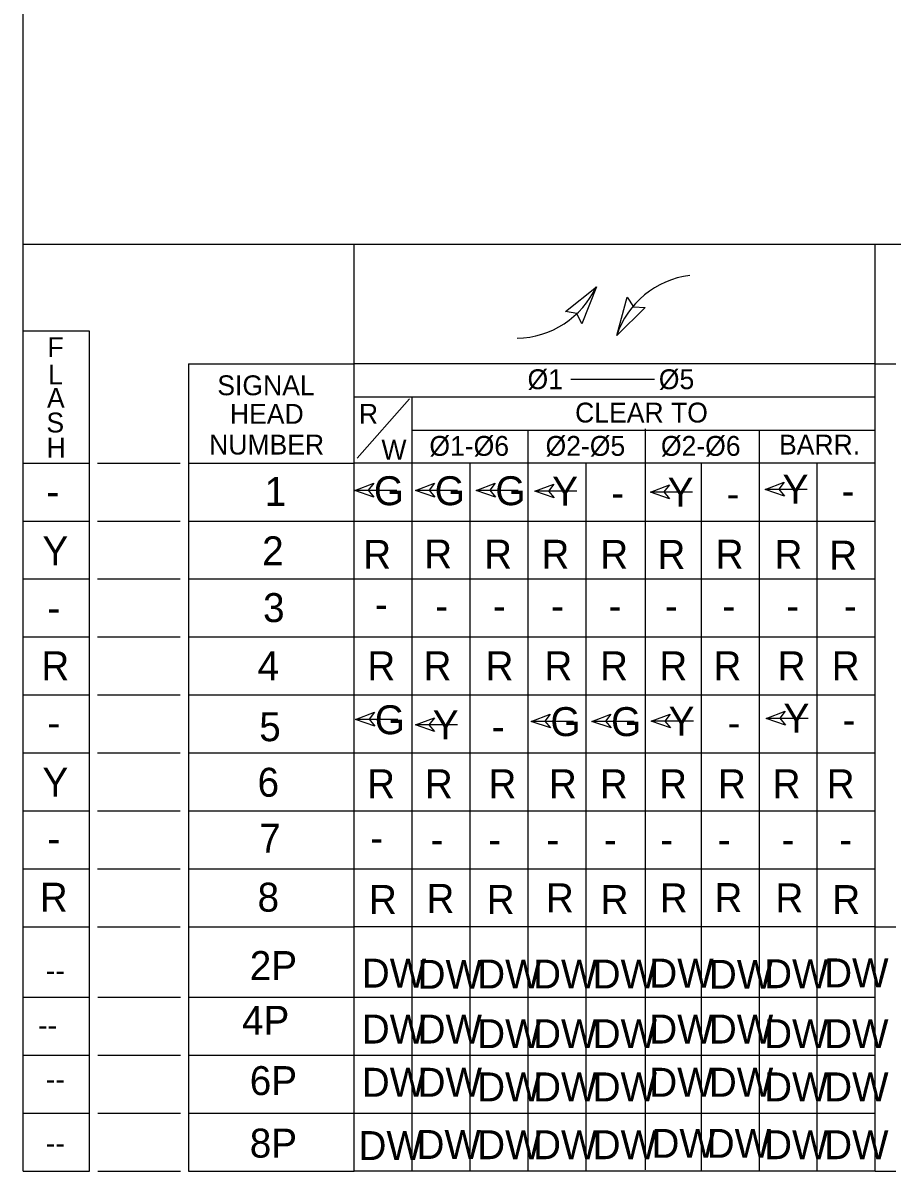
# Model space of a CAD drawing. Extents: x 0 to 3.01, y -0.05 to 1.83.
# Drawn here: x 2.2984 to 2.5103, y 1.2634 to 1.5432 of the extents above; entities that cross this region are included whole.
import ezdxf

# ---------------------------------------------------------------- set-up
doc = ezdxf.new("R2010")
doc.units = 0
for name, color, linetype in [('TR_TS_Border', 7, 'Continuous'), ('TR_TS_Phase1', 7, 'Continuous'), ('TR_TS_Phase2', 7, 'Continuous'), ('TR_TS_Phase3', 7, 'Continuous'), ('TR_TS_Phase4', 7, 'Continuous'), ('TR_TS_Phase5', 7, 'Continuous'), ('TR_TS_Phase6', 7, 'Continuous'), ('TR_TS_Phase7', 7, 'Continuous'), ('TR_TS_Phase8', 7, 'Continuous')]:
    doc.layers.add(name, color=color, linetype=linetype)

msp = doc.modelspace()

# ---------------------------------------------------------------- linework, layer by layer
at = {"layer": 'TR_TS_Border'}
for p, q in [((2.2983729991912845, 1.6927997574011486), (2.2983729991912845, 1.2634424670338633)), ((2.9074756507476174, 1.4891940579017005), (2.2983729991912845, 1.4891940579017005)), ((2.3790452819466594, 1.489194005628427), (2.3790452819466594, 1.2634422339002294)), ((2.506117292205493, 1.4891941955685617), (2.506117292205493, 1.2634424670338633)), ((2.2983729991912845, 1.4681904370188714), (2.31450758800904, 1.4681904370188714)), ((2.31450758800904, 1.4681904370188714), (2.31450758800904, 1.2634424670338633)), ((2.3387092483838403, 1.4601230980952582), (2.3790452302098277, 1.4601230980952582)), ((2.3387092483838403, 1.4601230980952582), (2.3387092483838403, 1.2634424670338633)), ((2.506117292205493, 1.4601230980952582), (2.3790452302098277, 1.4601230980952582)), ((2.506117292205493, 1.4601230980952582), (2.511179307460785, 1.4601230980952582)), ((2.431951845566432, 1.4563796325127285), (2.4523735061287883, 1.4563796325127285)), ((2.3790452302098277, 1.4520558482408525), (2.506117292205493, 1.4520558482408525)), ((2.3931761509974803, 1.4520558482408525), (2.3931761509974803, 1.2634424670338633)), ((2.379888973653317, 1.4371341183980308), (2.3925961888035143, 1.4515814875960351)), ((2.3931761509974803, 1.4439888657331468), (2.506117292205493, 1.4439888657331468)), ((2.421463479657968, 1.4439888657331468), (2.421463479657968, 1.2634424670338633)), ((2.450122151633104, 1.444253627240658), (2.450122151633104, 1.2637072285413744)), ((2.477908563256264, 1.4439888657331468), (2.477908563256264, 1.2634424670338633)), ((2.2983729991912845, 1.4359214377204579), (2.31450758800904, 1.4359214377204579)), ((2.316563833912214, 1.4359214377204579), (2.3367054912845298, 1.4359214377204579)), ((2.3387092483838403, 1.4359214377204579), (2.3790452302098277, 1.4359214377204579)), ((2.506117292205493, 1.4359214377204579), (2.3790452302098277, 1.4359214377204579)), ((2.4073326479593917, 1.4359214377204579), (2.4073326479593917, 1.2634424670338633)), ((2.435594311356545, 1.4359214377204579), (2.435594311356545, 1.2634424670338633)), ((2.463777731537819, 1.4359214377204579), (2.463777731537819, 1.2634424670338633)), ((2.4919864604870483, 1.4359214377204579), (2.4919864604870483, 1.2634424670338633)), ((2.2983729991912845, 1.4217904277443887), (2.31450758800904, 1.4217904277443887)), ((2.316563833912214, 1.4217904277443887), (2.3367054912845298, 1.4217904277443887)), ((2.3387092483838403, 1.4217904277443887), (2.506117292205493, 1.4217904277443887)), ((2.2983729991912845, 1.4077126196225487), (2.31450758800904, 1.4077126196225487)), ((2.316563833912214, 1.4077126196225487), (2.3367054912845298, 1.4077126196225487)), ((2.3387092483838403, 1.4077126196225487), (2.506117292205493, 1.4077126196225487)), ((2.2983729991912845, 1.39358169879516), (2.31450758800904, 1.39358169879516)), ((2.316563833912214, 1.39358169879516), (2.3367054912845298, 1.39358169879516)), ((2.3387092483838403, 1.39358169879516), (2.506117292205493, 1.39358169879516)), ((2.2983729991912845, 1.3794506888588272), (2.31450758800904, 1.3794506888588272)), ((2.316563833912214, 1.3794506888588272), (2.3367054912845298, 1.3794506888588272)), ((2.3387092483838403, 1.3794506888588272), (2.506117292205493, 1.3794506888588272)), ((2.2983729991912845, 1.365372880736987), (2.31450758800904, 1.365372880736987)), ((2.316563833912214, 1.365372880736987), (2.3367054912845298, 1.365372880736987)), ((2.3387092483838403, 1.365372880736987), (2.506117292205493, 1.365372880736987)), ((2.2983729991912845, 1.3512419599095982), (2.31450758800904, 1.3512419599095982)), ((2.316563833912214, 1.3512419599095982), (2.3367054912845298, 1.3512419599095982)), ((2.3387092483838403, 1.3512419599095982), (2.506117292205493, 1.3512419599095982)), ((2.2983729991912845, 1.3371109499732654), (2.31450758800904, 1.3371109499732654)), ((2.316563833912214, 1.3371109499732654), (2.3367054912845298, 1.3371109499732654)), ((2.3387092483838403, 1.3371109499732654), (2.506117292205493, 1.3371109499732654)), ((2.2983729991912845, 1.3229801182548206), (2.31450758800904, 1.3229801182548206)), ((2.316563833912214, 1.3229801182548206), (2.3367054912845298, 1.3229801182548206)), ((2.3387092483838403, 1.3229801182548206), (2.3790452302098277, 1.3229801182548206)), ((2.506117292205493, 1.3229801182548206), (2.3790452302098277, 1.3229801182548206)), ((2.506117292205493, 1.3229801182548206), (2.511179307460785, 1.3229801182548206)), ((2.298446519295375, 1.3058350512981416), (2.3145809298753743, 1.3058350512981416)), ((2.3166371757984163, 1.3058350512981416), (2.3367790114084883, 1.3058350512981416)), ((2.3387825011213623, 1.3058350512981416), (2.5061908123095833, 1.3058350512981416)), ((2.298446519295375, 1.2917041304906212), (2.3145809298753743, 1.2917041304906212)), ((2.3166371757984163, 1.2917041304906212), (2.3367790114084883, 1.2917041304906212)), ((2.3387825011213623, 1.2917041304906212), (2.5061908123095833, 1.2917041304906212)), ((2.298446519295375, 1.2775732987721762), (2.3145809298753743, 1.2775732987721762)), ((2.3166371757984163, 1.2775732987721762), (2.3367790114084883, 1.2775732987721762)), ((2.3387825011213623, 1.2775732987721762), (2.5061908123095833, 1.2775732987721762)), ((2.298446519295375, 1.2634424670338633), (2.3145809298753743, 1.2634424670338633)), ((2.3166371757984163, 1.2634424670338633), (2.3367790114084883, 1.2634424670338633)), ((2.3387825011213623, 1.2634424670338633), (2.379118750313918, 1.2634424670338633)), ((2.5061908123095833, 1.2634424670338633), (2.379118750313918, 1.2634424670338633)), ((2.5061908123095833, 1.2634424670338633), (2.5112527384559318, 1.2634424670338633))]:
    msp.add_line(p, q, dxfattribs=at)
at = {"layer": 'TR_TS_Phase1'}
for p, q in [((2.443227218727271, 1.4670472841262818), (2.4457458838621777, 1.4764021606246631)), ((2.4457458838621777, 1.4764021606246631), (2.4472570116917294, 1.474027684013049)), ((2.4500635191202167, 1.4738835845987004), (2.443227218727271, 1.4670472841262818)), ((2.4472570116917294, 1.474027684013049), (2.4500635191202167, 1.4738835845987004)), ((2.3792730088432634, 1.429266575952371), (2.3839074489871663, 1.4310291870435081)), ((2.3839074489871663, 1.4310291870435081), (2.382578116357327, 1.429325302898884)), ((2.394104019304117, 1.429266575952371), (2.398738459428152, 1.4310291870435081)), ((2.398738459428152, 1.4310291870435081), (2.3974091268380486, 1.429325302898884)), ((2.4088973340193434, 1.429266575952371), (2.4135318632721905, 1.4310291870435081)), ((2.4135318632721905, 1.4310291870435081), (2.4122024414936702, 1.429325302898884)), ((2.4232014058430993, 1.429071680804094), (2.4278357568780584, 1.4308344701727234)), ((2.4278357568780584, 1.4308344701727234), (2.4265065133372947, 1.4291304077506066)), ((2.451357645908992, 1.4288440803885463), (2.4559920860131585, 1.4306066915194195)), ((2.4559920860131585, 1.4306066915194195), (2.4546627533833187, 1.4289028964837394)), ((2.479378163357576, 1.4295275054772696), (2.484012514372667, 1.4312901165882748)), ((2.489639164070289, 1.4295275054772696), (2.479378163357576, 1.4295275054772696)), ((2.4840565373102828, 1.4279189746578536), (2.479378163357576, 1.4295275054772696)), ((2.484012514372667, 1.4312901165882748), (2.4826832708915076, 1.4295862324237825)), ((2.4826832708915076, 1.4295862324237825), (2.4840565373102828, 1.4279189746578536)), ((2.389534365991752, 1.429266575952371), (2.3792730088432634, 1.429266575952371)), ((2.383951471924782, 1.4276580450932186), (2.3792730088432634, 1.429266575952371)), ((2.382578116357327, 1.429325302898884), (2.383951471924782, 1.4276580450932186)), ((2.404365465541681, 1.429266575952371), (2.394104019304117, 1.429266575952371)), ((2.3987824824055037, 1.4276580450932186), (2.394104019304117, 1.429266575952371)), ((2.3974091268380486, 1.429325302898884), (2.3987824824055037, 1.4276580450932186)), ((2.4191586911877, 1.429266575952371), (2.4088973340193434, 1.429266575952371)), ((2.4135758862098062, 1.4276580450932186), (2.4088973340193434, 1.429266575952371)), ((2.4122024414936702, 1.429325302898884), (2.4135758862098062, 1.4276580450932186)), ((2.4334624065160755, 1.429071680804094), (2.4232014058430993, 1.429071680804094)), ((2.427879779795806, 1.4274633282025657), (2.4232014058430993, 1.429071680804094)), ((2.4265065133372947, 1.4291304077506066), (2.427879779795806, 1.4274633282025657)), ((2.46161873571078, 1.4288440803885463), (2.451357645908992, 1.4288440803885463)), ((2.456036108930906, 1.4272355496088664), (2.451357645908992, 1.4288440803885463)), ((2.4546627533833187, 1.4289028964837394), (2.456036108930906, 1.4272355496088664))]:
    msp.add_line(p, q, dxfattribs=at)
msp.add_arc((2.4636753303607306, 1.4602126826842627), 0.021617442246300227, 97.19140000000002, 161.63656666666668, dxfattribs=at)
at = {"layer": 'TR_TS_Phase5'}
for p, q in [((2.430661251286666, 1.4728688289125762), (2.4382011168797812, 1.4789204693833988)), ((2.4382011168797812, 1.4789204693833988), (2.434679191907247, 1.4698954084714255)), ((2.4334351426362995, 1.4724204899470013), (2.430661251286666, 1.4728688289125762)), ((2.434679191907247, 1.4698954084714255), (2.4334351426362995, 1.4724204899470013)), ((2.379500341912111, 1.3734607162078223), (2.3841347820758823, 1.3752235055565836)), ((2.3841347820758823, 1.3752235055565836), (2.382805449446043, 1.3735194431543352)), ((2.3940697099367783, 1.37212728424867), (2.398704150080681, 1.3738898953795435)), ((2.398704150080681, 1.3738898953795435), (2.397374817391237, 1.3721861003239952)), ((2.422325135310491, 1.3730050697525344), (2.426959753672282, 1.3747678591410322)), ((2.426959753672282, 1.3747678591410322), (2.4256302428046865, 1.3730637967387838)), ((2.4371185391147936, 1.3730050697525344), (2.4417531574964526, 1.3747678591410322)), ((2.4417531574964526, 1.3747678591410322), (2.4404236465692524, 1.3730637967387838)), ((2.4515850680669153, 1.3730382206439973), (2.456219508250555, 1.3748010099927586)), ((2.456219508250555, 1.3748010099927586), (2.454890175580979, 1.3730970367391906)), ((2.479605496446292, 1.3737216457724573), (2.4842399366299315, 1.375484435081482)), ((2.4898665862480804, 1.3737216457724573), (2.479605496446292, 1.3737216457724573)), ((2.4842839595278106, 1.3721131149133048), (2.479605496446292, 1.3737216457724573)), ((2.4842399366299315, 1.375484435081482), (2.4829106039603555, 1.3737803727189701)), ((2.4829106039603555, 1.3737803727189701), (2.4842839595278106, 1.3721131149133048)), ((2.3897617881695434, 1.3734607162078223), (2.379500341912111, 1.3734607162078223)), ((2.384178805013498, 1.3718523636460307), (2.379500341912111, 1.3734607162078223)), ((2.382805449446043, 1.3735194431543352), (2.384178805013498, 1.3718523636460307)), ((2.4043307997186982, 1.37212728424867), (2.3940697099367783, 1.37212728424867)), ((2.398748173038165, 1.3705187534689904), (2.3940697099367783, 1.37212728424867)), ((2.397374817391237, 1.3721861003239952), (2.398748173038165, 1.3705187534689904)), ((2.4325865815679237, 1.3730050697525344), (2.422325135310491, 1.3730050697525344)), ((2.4270037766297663, 1.3713965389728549), (2.422325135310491, 1.3730050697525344)), ((2.4256302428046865, 1.3730637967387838), (2.4270037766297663, 1.3713965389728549)), ((2.4473799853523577, 1.3730050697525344), (2.4371185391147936, 1.3730050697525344)), ((2.4417971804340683, 1.3713965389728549), (2.4371185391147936, 1.3730050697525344)), ((2.4404236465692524, 1.3730637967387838), (2.4417971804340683, 1.3713965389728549)), ((2.4618461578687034, 1.3730382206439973), (2.4515850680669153, 1.3730382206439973)), ((2.456263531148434, 1.3714296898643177), (2.4515850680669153, 1.3730382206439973)), ((2.454890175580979, 1.3730970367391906), (2.456263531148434, 1.3714296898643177))]:
    msp.add_line(p, q, dxfattribs=at)
msp.add_arc((2.4185162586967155, 1.4879885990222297), 0.021617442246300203, 270.9422666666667, 335.3874333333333, dxfattribs=at)

# ---------------------------------------------------------------- texts
at = {"layer": 'TR_TS_Border'}
for s, height, p in [('F', 0.004840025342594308, (2.304358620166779, 1.461756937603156)), ('L', 0.004840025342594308, (2.304483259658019, 1.4551132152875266)), ('Ø1             Ø5', 0.0048400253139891, (2.4214199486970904, 1.4539533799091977)), ('SIGNAL', 0.004840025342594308, (2.3457735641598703, 1.4524770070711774)), ('A', 0.004840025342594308, (2.304238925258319, 1.4494186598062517)), ('HEAD', 0.004840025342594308, (2.3488477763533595, 1.445516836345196)), ('R', 0.004840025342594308, (2.3802960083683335, 1.445516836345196)), ('CLEAR TO', 0.004840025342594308, (2.4330137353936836, 1.445833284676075)), ('S', 0.004840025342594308, (2.3040980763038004, 1.4434078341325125)), ('H', 0.004840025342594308, (2.3041231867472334, 1.437291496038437)), ('NUMBER', 0.004840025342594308, (2.3437709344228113, 1.438029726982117)), ('W', 0.004840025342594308, (2.385790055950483, 1.4368168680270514)), ('Ø1-Ø6', 0.004840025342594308, (2.39748467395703, 1.4377132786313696)), ('Ø2-Ø5', 0.004840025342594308, (2.4258099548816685, 1.4377132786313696)), ('Ø2-Ø6', 0.004840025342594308, (2.4539404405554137, 1.4377132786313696)), ('BARR.', 0.004840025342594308, (2.4827314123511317, 1.438029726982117))]:
    msp.add_text(s, height=height, rotation=360, dxfattribs=at).set_placement(p)
at = {"layer": 'TR_TS_Phase1'}
for s, p in [('1', (2.3573268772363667, 1.4255008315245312)), ('G', (2.3839499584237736, 1.4256844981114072)), ('G', (2.3987814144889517, 1.4256844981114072)), ('G', (2.4135748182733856, 1.4256844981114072)), ('Y', (2.4274309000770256, 1.4255827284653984)), ('Y', (2.4555873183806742, 1.4253552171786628)), ('Y', (2.4836076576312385, 1.426038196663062)), ('-', (2.3040972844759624, 1.4255008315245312)), ('-', (2.4418011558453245, 1.4252290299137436)), ('-', (2.4699575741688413, 1.4250015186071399)), ('-', (2.497977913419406, 1.4256844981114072))]:
    msp.add_text(s, height=0.007050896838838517, dxfattribs=at).set_placement(p)
at = {"layer": 'TR_TS_Phase2'}
for s, p in [('Y', (2.303127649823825, 1.4110400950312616)), ('2', (2.356703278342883, 1.4110400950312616))]:
    msp.add_text(s, height=0.007050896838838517, rotation=360, dxfattribs=at).set_placement(p)
for s, height, p in [('R', 0.007050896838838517, (2.381338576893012, 1.410179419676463)), ('R', 0.007050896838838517, (2.396208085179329, 1.4102638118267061)), ('R', 0.007050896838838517, (2.410811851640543, 1.4102436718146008)), ('R', 0.007050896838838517, (2.4248000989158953, 1.410204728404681)), ('R', 0.007050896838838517, (2.4391508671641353, 1.4101844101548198)), ('R', 0.007050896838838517, (2.453096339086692, 1.4101705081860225)), ('R', 0.007050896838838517, (2.467278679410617, 1.4102344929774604)), ('R', 0.007050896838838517, (2.4816307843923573, 1.410179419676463)), ('R', 0.007050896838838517, (2.494970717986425, 1.4099906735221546)), ('2P', 0.007050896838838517, (2.3536801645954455, 1.3099869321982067)), ('DW', 0.007050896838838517, (2.38099742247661, 1.3081454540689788)), ('DW', 0.007050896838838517, (2.3946009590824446, 1.3078440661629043)), ('DW', 0.007050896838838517, (2.40912897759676, 1.3079223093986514)), ('DW', 0.007050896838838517, (2.4227583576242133, 1.3079223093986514)), ('DW', 0.007050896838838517, (2.4372864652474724, 1.3079223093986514)), ('DW', 0.007050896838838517, (2.4510975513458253, 1.3081454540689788)), ('DW', 0.007050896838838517, (2.465625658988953, 1.3078440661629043)), ('DW', 0.007050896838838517, (2.4790991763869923, 1.3079986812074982)), ('DW', 0.007050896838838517, (2.493740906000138, 1.3081925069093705)), ('--', 0.005251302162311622, (2.30391307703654, 1.3097177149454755))]:
    msp.add_text(s, height=height, dxfattribs=at).set_placement(p)
at = {"layer": 'TR_TS_Phase3'}
for s, p in [('3', (2.3569246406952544, 1.3972038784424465)), ('-', (2.304338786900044, 1.3972038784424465)), ('-', (2.38420202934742, 1.3980887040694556)), ('-', (2.3989235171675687, 1.3976877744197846)), ('-', (2.412957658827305, 1.3976877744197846)), ('-', (2.427144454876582, 1.3976877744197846)), ('-', (2.441178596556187, 1.3976877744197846)), ('-', (2.454901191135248, 1.3976877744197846)), ('-', (2.468935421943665, 1.3976877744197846)), ('-', (2.484514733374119, 1.3976877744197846)), ('-', (2.4985490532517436, 1.3976877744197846))]:
    msp.add_text(s, height=0.007050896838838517, dxfattribs=at).set_placement(p)
at = {"layer": 'TR_TS_Phase4'}
for s, p in [('R', (2.3028560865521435, 1.3830324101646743)), ('4', (2.355583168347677, 1.3830324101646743)), ('R', (2.382351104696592, 1.3830324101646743)), ('R', (2.3960480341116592, 1.3830324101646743)), ('R', (2.4111716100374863, 1.3830324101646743)), ('R', (2.425519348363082, 1.3830324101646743)), ('R', (2.439091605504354, 1.3830324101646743)), ('R', (2.453557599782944, 1.3830324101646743)), ('R', (2.4667421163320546, 1.3830324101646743)), ('R', (2.482398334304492, 1.3830324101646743)), ('R', (2.4955828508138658, 1.3830324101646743))]:
    msp.add_text(s, height=0.007050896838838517, rotation=360, dxfattribs=at).set_placement(p)
for s, height, p in [('4P', 0.007050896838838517, (2.351795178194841, 1.2966357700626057)), ('DW', 0.007050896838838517, (2.38099742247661, 1.2945137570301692)), ('DW', 0.007050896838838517, (2.3946009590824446, 1.2945137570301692)), ('DW', 0.007050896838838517, (2.4510975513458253, 1.2945137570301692)), ('DW', 0.007050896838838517, (2.465625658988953, 1.2945137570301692)), ('--', 0.005251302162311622, (2.302028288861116, 1.296366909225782)), ('DW', 0.007050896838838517, (2.40912897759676, 1.2933867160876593)), ('DW', 0.007050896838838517, (2.4227583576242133, 1.2933867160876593)), ('DW', 0.007050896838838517, (2.4372864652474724, 1.2933867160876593)), ('DW', 0.007050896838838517, (2.4790991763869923, 1.2933867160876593)), ('DW', 0.007050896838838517, (2.493740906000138, 1.2933867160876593))]:
    msp.add_text(s, height=height, dxfattribs=at).set_placement(p)
at = {"layer": 'TR_TS_Phase5'}
for s, p in [('G', (2.384177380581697, 1.3698789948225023)), ('G', (2.4270023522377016, 1.369423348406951)), ('G', (2.4417957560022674, 1.369423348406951)), ('Y', (2.4558146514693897, 1.369549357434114)), ('Y', (2.483835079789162, 1.370232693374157)), ('5', (2.3559923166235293, 1.3681793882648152)), ('Y', (2.398299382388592, 1.3686384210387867)), ('-', (2.3043223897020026, 1.3692051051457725)), ('-', (2.4126696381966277, 1.368284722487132)), ('-', (2.470184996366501, 1.3691956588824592)), ('-', (2.498205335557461, 1.3698789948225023))]:
    msp.add_text(s, height=0.007050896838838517, dxfattribs=at).set_placement(p)
at = {"layer": 'TR_TS_Phase6'}
for s, p in [('Y', (2.303127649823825, 1.3546514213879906)), ('6', (2.3555830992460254, 1.3546514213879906))]:
    msp.add_text(s, height=0.007050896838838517, rotation=360, dxfattribs=at).set_placement(p)
for s, height, p in [('R', 0.007050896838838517, (2.3822872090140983, 1.3542794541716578)), ('R', 0.007050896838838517, (2.3963719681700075, 1.3542794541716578)), ('R', 0.007050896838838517, (2.4118832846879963, 1.3542794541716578)), ('R', 0.007050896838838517, (2.4266189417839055, 1.3542794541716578)), ('R', 0.007050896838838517, (2.4390277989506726, 1.3542794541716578)), ('R', 0.007050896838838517, (2.4534937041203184, 1.3542794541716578)), ('R', 0.007050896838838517, (2.4678415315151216, 1.3542794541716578)), ('R', 0.007050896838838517, (2.481171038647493, 1.3542794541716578)), ('R', 0.007050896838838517, (2.4943557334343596, 1.3542794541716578)), ('6P', 0.007050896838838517, (2.3536801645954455, 1.281951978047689)), ('DW', 0.007050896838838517, (2.38099742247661, 1.281551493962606)), ('DW', 0.007050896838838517, (2.3946009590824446, 1.281551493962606)), ('DW', 0.007050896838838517, (2.40912897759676, 1.280424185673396)), ('DW', 0.007050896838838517, (2.4227583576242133, 1.280424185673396)), ('DW', 0.007050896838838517, (2.4372864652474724, 1.280424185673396)), ('DW', 0.007050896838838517, (2.4510975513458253, 1.281551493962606)), ('DW', 0.007050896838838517, (2.465625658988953, 1.281551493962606)), ('DW', 0.007050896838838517, (2.4790991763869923, 1.280424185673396)), ('DW', 0.007050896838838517, (2.493740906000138, 1.280424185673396)), ('--', 0.005251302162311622, (2.30391307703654, 1.2832412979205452))]:
    msp.add_text(s, height=height, dxfattribs=at).set_placement(p)
at = {"layer": 'TR_TS_Phase7'}
for s, p in [('7', (2.3559923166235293, 1.3410038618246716)), ('-', (2.3043223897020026, 1.3410038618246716)), ('-', (2.383063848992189, 1.341144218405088)), ('-', (2.3977853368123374, 1.3407432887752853)), ('-', (2.411819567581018, 1.3407432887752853)), ('-', (2.4260066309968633, 1.3407432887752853)), ('-', (2.4400407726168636, 1.3407432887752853)), ('-', (2.4537630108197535, 1.3407432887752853)), ('-', (2.4677974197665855, 1.3407432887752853)), ('-', (2.483376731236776, 1.3407432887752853)), ('-', (2.497410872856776, 1.3407432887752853))]:
    msp.add_text(s, height=0.007050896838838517, dxfattribs=at).set_placement(p)
at = {"layer": 'TR_TS_Phase8'}
for s, p in [('R', (2.302482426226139, 1.3266437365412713)), ('8', (2.3555830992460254, 1.3266437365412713))]:
    msp.add_text(s, height=0.007050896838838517, rotation=360, dxfattribs=at).set_placement(p)
for s, height, p in [('R', 0.007050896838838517, (2.382742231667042, 1.326088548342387)), ('R', 0.007050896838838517, (2.396760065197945, 1.3263423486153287)), ('R', 0.007050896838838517, (2.4114562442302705, 1.326088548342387)), ('R', 0.007050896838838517, (2.425891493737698, 1.3264898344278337)), ('R', 0.007050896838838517, (2.4392219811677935, 1.326088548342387)), ('R', 0.007050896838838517, (2.453648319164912, 1.3264898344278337)), ('R', 0.007050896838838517, (2.466978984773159, 1.326543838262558)), ('R', 0.007050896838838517, (2.4818405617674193, 1.3264898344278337)), ('R', 0.007050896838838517, (2.495723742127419, 1.3260609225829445)), ('8P', 0.007050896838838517, (2.3536801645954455, 1.266714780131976)), ('DW', 0.007050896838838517, (2.3801985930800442, 1.2661297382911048)), ('DW', 0.007050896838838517, (2.3943345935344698, 1.266396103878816)), ('DW', 0.007050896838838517, (2.40912897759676, 1.2663344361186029)), ('DW', 0.007050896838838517, (2.4227583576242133, 1.2663344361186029)), ('DW', 0.007050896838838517, (2.4372864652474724, 1.2663344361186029)), ('DW', 0.007050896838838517, (2.4516301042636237, 1.2666626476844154)), ('DW', 0.007050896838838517, (2.4650930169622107, 1.2666626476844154)), ('DW', 0.007050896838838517, (2.4790991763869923, 1.2663344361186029)), ('DW', 0.007050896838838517, (2.493740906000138, 1.2663344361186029)), ('--', 0.005251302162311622, (2.30391307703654, 1.2676144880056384))]:
    msp.add_text(s, height=height, dxfattribs=at).set_placement(p)

doc.saveas('drawing.dxf')
